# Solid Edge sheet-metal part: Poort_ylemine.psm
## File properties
Author: haldur
Template: Normal.psm
Last saved by: haldur
Revision: 9
Application: Solid Edge
Accuracy: 0,990
Material Thickness: 0,50 mm
Bend Radius: 1,00 mm
Relief Width: 1,00 mm
Relief Length: 0,00 mm
Neutral Factor: 0,330
Minimum Arc Length: 0,10 mm
Deviational Tolerance: 0,10 mm
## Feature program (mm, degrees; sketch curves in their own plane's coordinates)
base tab "unnamed BaseTab 1"
flange "Flange_1"
flange "Flange_2"
dimple "Dimple_1"
dimple "Dimple_2"
dimple "unnamed Dimple 1"
pattern "unnamed Pattern 1" of "unnamed Dimple 1"
dimple "unnamed Dimple 2"
dimple "unnamed Dimple 3"
dimple "unnamed Dimple 4"
dimple "unnamed Dimple 5"
dimple "unnamed Dimple 6"
dimple "unnamed Dimple 7"
dimple "unnamed Dimple 8"
dimple "unnamed Dimple 9"
dimple "unnamed Dimple 10"
pattern "unnamed Pattern 2" of "unnamed Dimple 10"
dimple "unnamed Dimple 11"
dimple "unnamed Dimple 12"
dimple "unnamed Dimple 13"
dimple "unnamed Dimple 14"
dimple "unnamed Dimple 15"
dimple "unnamed Dimple 16"
dimple "unnamed Dimple 17"
dimple "unnamed Dimple 18"
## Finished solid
Body 1: solid body, 194 faces, 468 edges, 312 vertices.
  Faces by surface: cylinder 148, plane 46
  Edges by curve: line 316, ellipse 144, circle 8
Bounding box of the edges (mm): 273.800 x 64.000 x 5.000, from (-273.8, -32, 0) to (0, 32, 5).
Cylindrical faces by radius (mm): R0.5 x144, R1 x2, R1.5 x2
Planar faces by outward normal: +x 3, +y 18, +z 1, -x 5, -y 18, -z 1
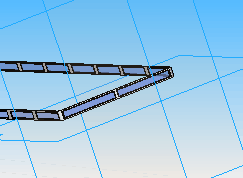
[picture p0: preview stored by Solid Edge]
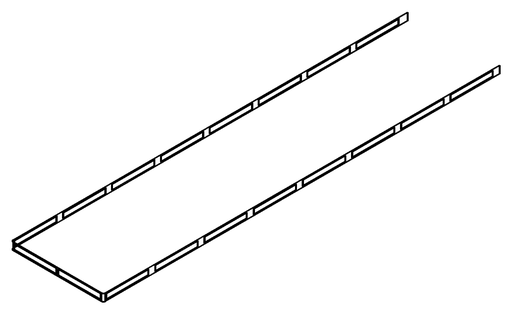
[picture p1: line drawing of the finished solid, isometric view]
